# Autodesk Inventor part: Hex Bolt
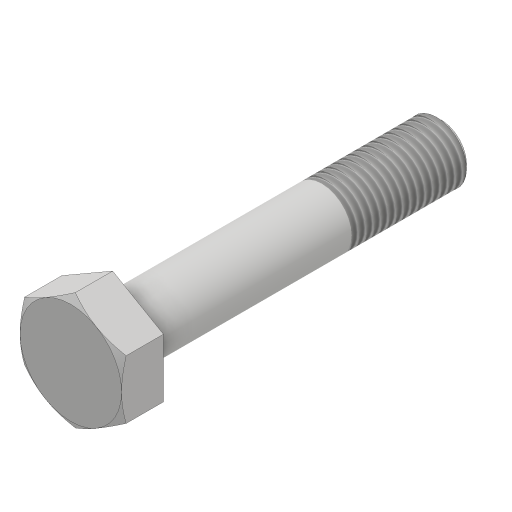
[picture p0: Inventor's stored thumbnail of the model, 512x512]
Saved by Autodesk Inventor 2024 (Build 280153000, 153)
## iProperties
Created: 2016-05
Part Number: Hex Bolt
Material: Generic
Document SubType Name: Modeling
Designer: CADCIM
Density: 1 g/cm^3
Appearance: Default
Author: CADCIM
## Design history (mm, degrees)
sketch "Sketch1"
  geometry: L1 (0, -19.63)-(-17, -9.815); L2 (-17, -9.815)-(-17, 9.815); L3 (-17, 9.815)-(0, 19.63); L4 (0, 19.63)-(17, 9.815); L5 (17, 9.815)-(17, -9.815); L6 (17, -9.815)-(0, -19.63); 2 further points
  constraints: 12 end point, 1 coincident, 13 other
  dimensions: "d0" = 34 distance between parallel lines of L2 L5
extrude "Extrusion1" new body sketch "Sketch1" distance "d1" = 14; taper "d2" = 0 deg
sketch "Sketch3"
  geometry: C1 r 10 at (0, 0); 1 further point
  constraints: 1 centre point, 1 coincident
  dimensions: "d3" = 20 diameter of C1
extrude "Extrusion2" join sketch "Sketch3" distance "d4" = 110; taper "d5" = 0 deg
thread "Thread1" dims "d6" = 40, "d7" = 0
sketch "Sketch4"
  geometry: L1 (0, -19.63)-(17, -9.815) reference; C1 r 17 at (0, 0); 1 further point
  constraints: 1 centre point, 1 coincident, 1 tangent
extrude "Extrusion3" sketch "Sketch4" distance "d8" = 200; taper "d9" = 60 deg
chamfer "Chamfer1" distance "d10" = 1.5; stored, may be unused: second distance "d11" = 2, angle "d12" = 45 deg
body "Solid1"
sketch "Sketch2"
  geometry: 1 further point
